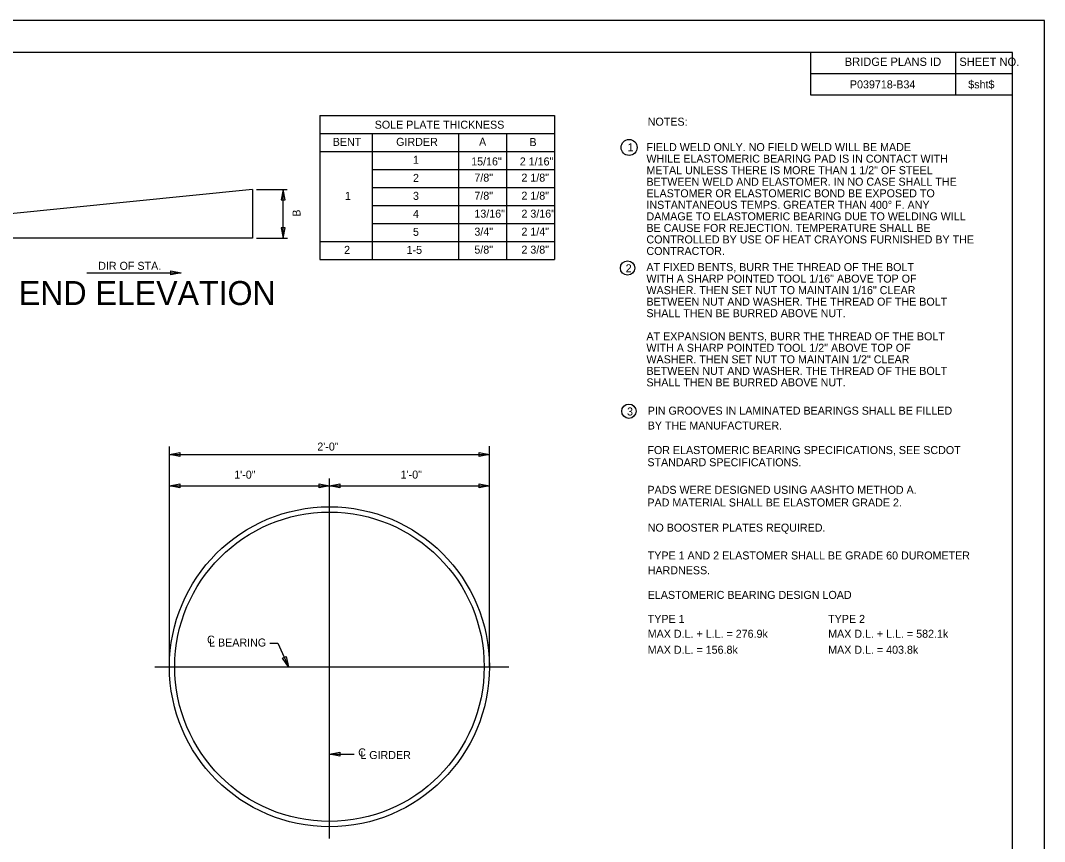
# Model space of a CAD drawing. Extents: x -125.5 to -89.4, y -5.1 to 16.9.
# Drawn here: x -105.53 to -89.53, y 4.11 to 16.93 of the extents above; entities that cross this region are included whole.
import ezdxf

# ---------------------------------------------------------------- set-up
doc = ezdxf.new("R2010")
doc.units = 0
for name, color, linetype in [('BR_AUTO DIMENSION', 7, 'Continuous'), ('BR_BORDER LINES', 7, 'Continuous'), ('BR_CENTER LINES', 7, 'Continuous'), ('BR_STRUCTURAL STEEL', 7, 'Continuous'), ('BR_TABLE LINES', 7, 'Continuous'), ('BR_TEXT', 7, 'Continuous'), ('Level 31', 7, 'Continuous')]:
    doc.layers.add(name, color=color, linetype=linetype)

msp = doc.modelspace()

# ---------------------------------------------------------------- linework, layer by layer
at = {"layer": 'BR_AUTO DIMENSION'}
for p, q in [((-101.846, 14.295), (-101.364, 14.295)), ((-101.427, 13.53), (-101.427, 14.295)), ((-101.846, 13.53), (-101.358, 13.53)), ((-104.495, 12.991), (-103.02, 12.991)), ((-103.204, 8.349), (-103.204, 10.278)), ((-98.204, 8.349), (-98.204, 10.283)), ((-103.204, 10.151), (-98.204, 10.151)), ((-103.204, 9.661), (-98.204, 9.661)), ((-103.204, 6.836), (-103.204, 8.77)), ((-98.204, 6.836), (-98.204, 8.77)), ((-101.638, 7.207), (-101.513, 7.207)), ((-101.513, 7.207), (-101.344, 6.836)), ((-100.706, 5.469), (-100.316, 5.469))]:
    msp.add_line(p, q, dxfattribs=at)
for points in [[(-101.396, 14.132), (-101.427, 14.295), (-101.458, 14.132)], [(-101.458, 13.693), (-101.427, 13.53), (-101.396, 13.693)], [(-103.183, 13.022), (-103.02, 12.991), (-103.183, 12.96)], [(-103.042, 10.12), (-103.204, 10.151), (-103.042, 10.182)], [(-98.367, 10.182), (-98.204, 10.151), (-98.367, 10.12)], [(-103.042, 9.63), (-103.204, 9.661), (-103.042, 9.693)], [(-100.867, 9.693), (-100.704, 9.661), (-100.867, 9.63)], [(-100.542, 9.63), (-100.704, 9.661), (-100.542, 9.693)], [(-98.367, 9.693), (-98.204, 9.661), (-98.367, 9.63)], [(-101.383, 6.996), (-101.344, 6.836), (-101.44, 6.971)], [(-100.543, 5.438), (-100.706, 5.469), (-100.543, 5.501)]]:
    msp.add_lwpolyline(points, close=True, dxfattribs=at)
for centre, radius in [((-96.023, 14.95), 0.125), ((-96.047, 13.066), 0.112), ((-96.026, 10.829), 0.112)]:
    msp.add_circle(centre, radius, dxfattribs=at)
at = {"layer": 'BR_BORDER LINES'}
for p, q in [((-90.033, 16.434), (-123.699, 16.434)), ((-93.186, 15.767), (-93.186, 16.434)), ((-90.919, 15.767), (-90.919, 16.434)), ((-90.033, -4.566), (-90.033, 16.434)), ((-93.186, 16.104), (-90.033, 16.104)), ((-90.919, 16.104), (-90.033, 16.104)), ((-90.033, 15.767), (-93.186, 15.767))]:
    msp.add_line(p, q, dxfattribs=at)
at = {"layer": 'BR_CENTER LINES'}
for p, q in [((-100.704, 4.152), (-100.704, 9.777)), ((-103.432, 6.836), (-97.902, 6.836))]:
    msp.add_line(p, q, dxfattribs=at)
at = {"layer": 'BR_STRUCTURAL STEEL'}
for p, q in [((-101.906, 14.291), (-105.739, 13.91)), ((-101.906, 14.291), (-101.906, 13.91)), ((-101.906, 13.91), (-101.906, 13.53)), ((-101.906, 13.53), (-105.739, 13.53))]:
    msp.add_line(p, q, dxfattribs=at)
for radius in [2.5, 2.417]:
    msp.add_circle((-100.704, 6.836), radius, dxfattribs=at)
at = {"layer": 'BR_TABLE LINES'}
for p, q in [((-100.856, 15.449), (-97.19, 15.449)), ((-100.856, 15.449), (-100.856, 13.199)), ((-97.19, 15.449), (-97.19, 13.199)), ((-100.856, 15.168), (-97.19, 15.168)), ((-100.036, 15.168), (-100.036, 13.199)), ((-98.69, 15.168), (-98.69, 13.199)), ((-97.94, 15.168), (-97.94, 13.199)), ((-100.856, 14.887), (-97.19, 14.887)), ((-100.036, 14.606), (-97.19, 14.606)), ((-100.036, 14.324), (-97.19, 14.324)), ((-100.036, 14.043), (-97.19, 14.043)), ((-100.036, 13.762), (-97.19, 13.762)), ((-100.856, 13.481), (-97.19, 13.481)), ((-100.856, 13.199), (-97.19, 13.199))]:
    msp.add_line(p, q, dxfattribs=at)
at = {"layer": 'Level 31'}
msp.add_line((-89.533, 16.934), (-125.533, 16.934), dxfattribs=at)
msp.add_lwpolyline([(-125.533, 16.934), (-125.533, -5.066), (-89.533, -5.066), (-89.533, 16.934)], dxfattribs=at)

# ---------------------------------------------------------------- texts
at = {"layer": 'BR_TEXT'}
for s, height, p in [('BRIDGE PLANS ID', 0.13, (-92.654, 16.224)), ('SHEET NO.', 0.13, (-90.864, 16.224)), ('P039718-B34', 0.125, (-92.573, 15.873)), ('$sht$', 0.125, (-90.724, 15.873)), ('SOLE PLATE THICKNESS', 0.125, (-99.997, 15.243)), ('NOTES:', 0.125, (-95.732, 15.29)), ('BENT', 0.125, (-100.653, 14.975)), ('GIRDER', 0.125, (-99.662, 14.975)), ('A', 0.125, (-98.367, 14.976)), ('B', 0.125, (-97.58, 14.972)), ('1', 0.125, (-96.047, 14.89)), ('FIELD WELD ONLY. NO FIELD WELD WILL BE MADE ', 0.125, (-95.752, 14.893)), ('1', 0.125, (-99.399, 14.694)), ('15/16"', 0.125, (-98.49, 14.669)), ('2 1/16"', 0.125, (-97.731, 14.669)), ('WHILE ELASTOMERIC BEARING PAD IS IN CONTACT WITH ', 0.125, (-95.752, 14.712)), ('METAL UNLESS THERE IS MORE THAN 1 1/2" OF STEEL ', 0.125, (-95.752, 14.532)), ('2', 0.125, (-99.399, 14.412)), ('7/8"', 0.125, (-98.44, 14.416)), ('2 1/8"', 0.125, (-97.705, 14.416)), ('BETWEEN WELD AND ELASTOMER. IN NO CASE SHALL THE ', 0.125, (-95.752, 14.352)), ('1', 0.125, (-100.463, 14.131)), ('3', 0.125, (-99.399, 14.131)), ('7/8"', 0.125, (-98.44, 14.134)), ('2 1/8"', 0.125, (-97.705, 14.134)), ('ELASTOMER OR ELASTOMERIC BOND BE EXPOSED TO ', 0.125, (-95.752, 14.171)), ('INSTANTANEOUS TEMPS. GREATER THAN 400%%d F. ANY ', 0.125, (-95.752, 13.991)), ('4', 0.125, (-99.399, 13.85)), ('13/16"', 0.125, (-98.44, 13.853)), ('2 3/16"', 0.125, (-97.705, 13.853)), ('DAMAGE TO ELASTOMERIC BEARING DUE TO WELDING WILL ', 0.125, (-95.752, 13.811)), ('5', 0.125, (-99.399, 13.569)), ('3/4"', 0.125, (-98.44, 13.572)), ('2 1/4"', 0.125, (-97.705, 13.572)), ('BE CAUSE FOR REJECTION. TEMPERATURE SHALL BE ', 0.125, (-95.752, 13.63)), ('CONTROLLED BY USE OF HEAT CRAYONS FURNISHED BY THE ', 0.125, (-95.752, 13.45)), ('2', 0.125, (-100.475, 13.287)), ('1-5', 0.125, (-99.499, 13.287)), ('5/8"', 0.125, (-98.44, 13.291)), ('2 3/8"', 0.125, (-97.705, 13.291)), ('CONTRACTOR.', 0.125, (-95.752, 13.27)), ('DIR OF STA.', 0.125, (-104.317, 13.038)), ('2', 0.125, (-96.076, 12.999)), ('AT FIXED BENTS, BURR THE THREAD OF THE BOLT', 0.125, (-95.752, 13.018)), ('WITH A SHARP POINTED TOOL 1/16" ABOVE TOP OF', 0.125, (-95.752, 12.838)), ('END ELEVATION', 0.375, (-105.557, 12.488)), ('WASHER. THEN SET NUT TO MAINTAIN 1/16" CLEAR', 0.125, (-95.752, 12.658)), ('BETWEEN NUT AND WASHER. THE THREAD OF THE BOLT', 0.125, (-95.752, 12.478)), ('SHALL THEN BE BURRED ABOVE NUT.', 0.125, (-95.752, 12.298)), ('AT EXPANSION BENTS, BURR THE THREAD OF THE BOLT', 0.125, (-95.752, 11.937)), ('WITH A SHARP POINTED TOOL 1/2" ABOVE TOP OF', 0.125, (-95.752, 11.757)), ('WASHER. THEN SET NUT TO MAINTAIN 1/2" CLEAR', 0.125, (-95.752, 11.577)), ('BETWEEN NUT AND WASHER. THE THREAD OF THE BOLT', 0.125, (-95.752, 11.397)), ('SHALL THEN BE BURRED ABOVE NUT.', 0.125, (-95.752, 11.217)), ('3', 0.125, (-96.055, 10.762)), ('PIN GROOVES IN LAMINATED BEARINGS SHALL BE FILLED', 0.125, (-95.732, 10.775)), ('BY THE MANUFACTURER.', 0.125, (-95.732, 10.543)), ('2\'-0"', 0.125, (-100.894, 10.214)), ('FOR ELASTOMERIC BEARING SPECIFICATIONS, SEE SCDOT', 0.125, (-95.737, 10.159)), ('STANDARD SPECIFICATIONS.', 0.125, (-95.737, 9.969)), ('1\'-0"', 0.125, (-102.192, 9.775)), ('1\'-0"', 0.125, (-99.592, 9.776)), ('PADS WERE DESIGNED USING AASHTO METHOD A.', 0.125, (-95.737, 9.538)), ('PAD MATERIAL SHALL BE ELASTOMER GRADE 2.', 0.125, (-95.737, 9.34)), ('NO BOOSTER PLATES REQUIRED.', 0.125, (-95.732, 8.947)), ('TYPE 1 AND 2 ELASTOMER SHALL BE GRADE 60 DUROMETER', 0.125, (-95.732, 8.512)), ('HARDNESS.', 0.125, (-95.732, 8.281)), ('ELASTOMERIC BEARING DESIGN LOAD', 0.125, (-95.732, 7.896)), ('TYPE 1', 0.125, (-95.732, 7.521)), ('TYPE 2', 0.125, (-92.913, 7.521)), ('MAX D.L. + L.L. = 276.9k', 0.125, (-95.732, 7.289)), ('MAX D.L. + L.L. = 582.1k', 0.125, (-92.913, 7.289)), ('MAX D.L. = 156.8k', 0.125, (-95.732, 7.039)), ('MAX D.L. = 403.8k', 0.125, (-92.913, 7.039)), ('C', 0.125, (-100.255, 5.435)), ('L GIRDER', 0.125, (-100.222, 5.394))]:
    msp.add_text(s, height=height, dxfattribs=at).set_placement(p)
for s, rotation, p in [('B', 90, (-101.156, 13.868)), ('C', 360, (-102.616, 7.197)), ('L BEARING', 360, (-102.585, 7.152))]:
    msp.add_text(s, height=0.125, rotation=rotation, dxfattribs=at).set_placement(p)

doc.saveas('drawing.dxf')
